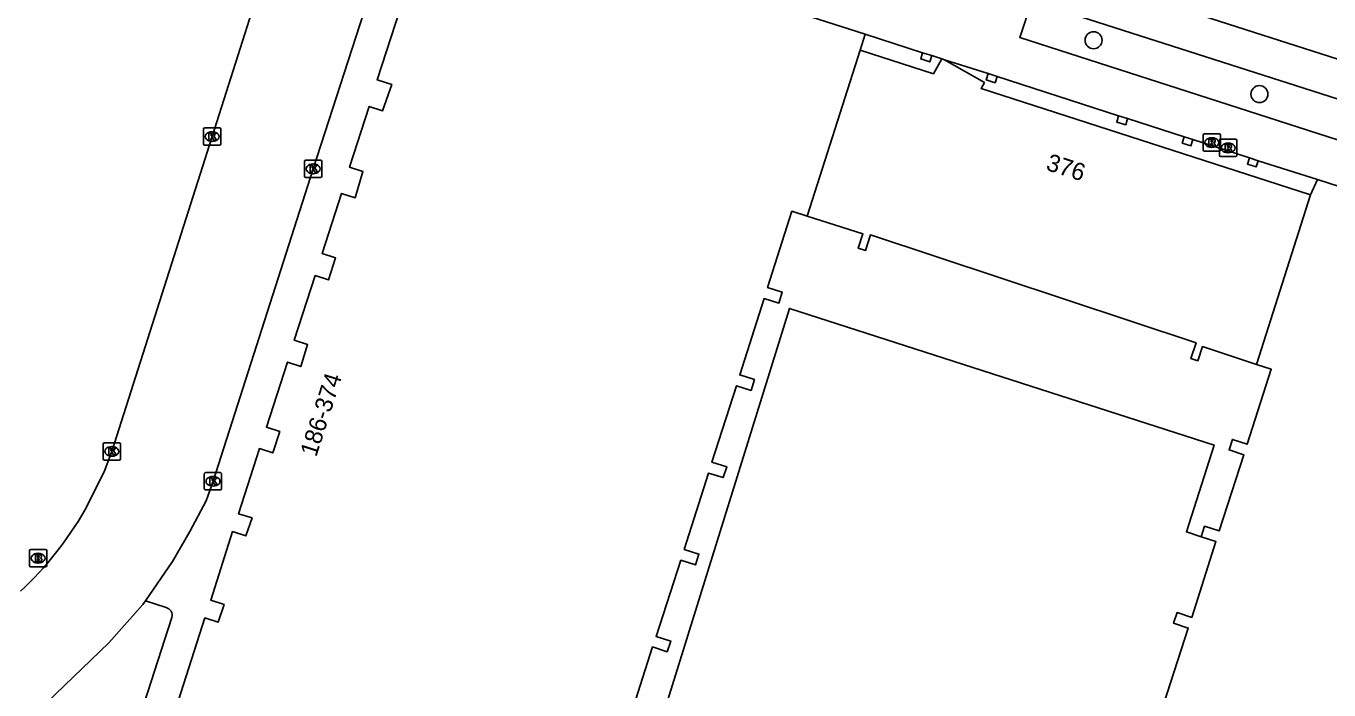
# Model space of a CAD drawing. Extents: x 160676 to 161153, y 383244 to 383713.
# Drawn here: x 160812.1 to 160887.3, y 383366.1 to 383404.4 of the extents above; entities that cross this region are included whole.
import ezdxf

# ---------------------------------------------------------------- set-up
doc = ezdxf.new("R2010")
doc.units = 0
for name, color, linetype in [('IMGEO_Boom', 7, 'Continuous'), ('IMGEO_Brandkraan', 7, 'Continuous'), ('IMGEO_Erf', 7, 'Continuous'), ('IMGEO_Kolk', 7, 'Continuous'), ('IMGEO_Muur', 7, 'Continuous'), ('IMGEO_Pand', 7, 'Continuous'), ('IMGEO_Pand_nummerreeks', 7, 'Continuous'), ('IMGEO_Parkeervlak_open', 7, 'Continuous'), ('IMGEO_Rijbaan_lokaal_open', 7, 'Continuous'), ('IMGEO_Rioolput', 7, 'Continuous'), ('IMGEO_Voetpad_open', 7, 'Continuous')]:
    doc.layers.add(name, color=color, linetype=linetype)

msp = doc.modelspace()

# ---------------------------------------------------------------- linework, layer by layer
at = {"layer": 'IMGEO_Boom'}
for centre in [(160873.692, 383403.537), (160883.26, 383400.432)]:
    msp.add_circle(centre, 0.489, dxfattribs=at)
at = {"layer": 'IMGEO_Brandkraan'}
for p, q in [((160812.259, 383373.243), (160812.259, 383374.095)), ((160812.334, 383374.169), (160813.186, 383374.169)), ((160812.747, 383373.949), (160812.772, 383373.949)), ((160813.26, 383374.095), (160813.26, 383373.243)), ((160813.186, 383373.169), (160812.334, 383373.169)), ((160812.77, 383373.389), (160812.745, 383373.389))]:
    msp.add_line(p, q, dxfattribs=at)
for points in [[(160812.259, 383373.243), (160812.259, 383374.095)], [(160812.334, 383374.169), (160813.186, 383374.169)], [(160812.607, 383373.869), (160812.607, 383373.469), (160812.82, 383373.469)], [(160812.838, 383373.869), (160812.607, 383373.869)], [(160813.26, 383374.095), (160813.26, 383373.243)], [(160813.186, 383373.169), (160812.334, 383373.169)], [(160812.786, 383373.788), (160812.732, 383373.788), (160812.732, 383373.712)], [(160812.732, 383373.712), (160812.785, 383373.712)], [(160812.794, 383373.636), (160812.732, 383373.636), (160812.732, 383373.555)], [(160812.732, 383373.555), (160812.794, 383373.555)]]:
    msp.add_lwpolyline(points, dxfattribs=at)
for centre, radius, start, end in [((160812.336, 383374.093), 0.0765, 91.55205, 178.44795), ((160812.336, 383374.093), 0.0765, 91.55205, 178.44795), ((160812.842, 383373.724), 0.145, 59.4692, 91.53667), ((160812.867, 383373.771), 0.0922, 285.51372, 58.15012), ((160813.184, 383374.093), 0.0765, 1.55205, 88.44795), ((160813.184, 383374.093), 0.0765, 1.55205, 88.44795), ((160812.336, 383373.245), 0.0765, 181.55205, 268.44795), ((160812.336, 383373.245), 0.0765, 181.55205, 268.44795), ((160812.787, 383373.75), 0.0379, 267.82845, 90.93552), ((160812.795, 383373.595), 0.0404, 269.87594, 90.50774), ((160812.826, 383373.72), 0.251, 268.66757, 293.53466), ((160812.872, 383373.579), 0.105, 301.31148, 78.98903), ((160813.184, 383373.245), 0.0765, 271.55205, 358.44795), ((160813.184, 383373.245), 0.0765, 271.55205, 358.44795)]:
    msp.add_arc(centre, radius, start, end, dxfattribs=at)
for centre, major_axis, ratio, start_param, end_param in [((160812.746, 383373.669), (-0.387, 0.002), 0.722429, 4.712389, 7.853982), ((160812.771, 383373.669), (-0.39, 0.002), 0.717154, 1.570796, 4.712389)]:
    msp.add_ellipse(centre, major_axis=major_axis, ratio=ratio, start_param=start_param, end_param=end_param, dxfattribs=at)
at = {"layer": 'IMGEO_Erf'}
msp.add_lwpolyline([(160879.905, 383374.906), (160879.048, 383375.181), (160880.657, 383380.189), (160856.132, 383388.071), (160842.086, 383342.926)], dxfattribs=at)
at = {"layer": 'IMGEO_Kolk'}
for p, q in [((160822.305, 383397.558), (160822.305, 383398.41)), ((160822.38, 383398.484), (160823.232, 383398.484)), ((160822.793, 383398.264), (160822.818, 383398.264)), ((160823.306, 383398.41), (160823.306, 383397.558)), ((160823.232, 383397.484), (160822.38, 383397.484)), ((160822.816, 383397.704), (160822.791, 383397.704)), ((160828.141, 383395.698), (160828.141, 383396.55)), ((160828.216, 383396.624), (160829.068, 383396.624)), ((160828.629, 383396.404), (160828.654, 383396.404)), ((160829.142, 383396.55), (160829.142, 383395.698)), ((160828.652, 383395.844), (160828.627, 383395.844)), ((160829.068, 383395.624), (160828.216, 383395.624)), ((160816.518, 383379.4), (160816.518, 383380.252)), ((160816.593, 383380.326), (160817.445, 383380.326)), ((160817.006, 383380.106), (160817.031, 383380.106)), ((160817.519, 383380.252), (160817.519, 383379.4)), ((160817.445, 383379.326), (160816.593, 383379.326)), ((160817.029, 383379.546), (160817.004, 383379.546)), ((160822.356, 383377.677), (160822.356, 383378.529)), ((160822.431, 383378.603), (160823.283, 383378.603)), ((160822.844, 383378.383), (160822.869, 383378.383)), ((160823.357, 383378.529), (160823.357, 383377.677)), ((160823.283, 383377.603), (160822.431, 383377.603)), ((160822.867, 383377.823), (160822.842, 383377.823))]:
    msp.add_line(p, q, dxfattribs=at)
for points in [[(160822.305, 383397.558), (160822.305, 383398.41)], [(160822.38, 383398.484), (160823.232, 383398.484)], [(160822.626, 383398.184), (160822.749, 383398.184), (160822.749, 383398.033), (160822.879, 383398.184), (160823.043, 383398.184), (160822.897, 383398.033), (160823.05, 383397.784), (160822.898, 383397.784), (160822.813, 383397.948), (160822.749, 383397.881), (160822.749, 383397.784), (160822.626, 383397.784), (160822.626, 383398.184)], [(160823.306, 383398.41), (160823.306, 383397.558)], [(160823.232, 383397.484), (160822.38, 383397.484)], [(160828.141, 383395.698), (160828.141, 383396.55)], [(160828.216, 383396.624), (160829.068, 383396.624)], [(160829.142, 383396.55), (160829.142, 383395.698)], [(160828.462, 383396.324), (160828.585, 383396.324), (160828.585, 383396.173), (160828.715, 383396.324), (160828.879, 383396.324), (160828.733, 383396.173), (160828.886, 383395.924), (160828.734, 383395.924), (160828.649, 383396.088), (160828.585, 383396.021), (160828.585, 383395.924), (160828.462, 383395.924), (160828.462, 383396.324)], [(160829.068, 383395.624), (160828.216, 383395.624)], [(160816.518, 383379.4), (160816.518, 383380.252)], [(160816.593, 383380.326), (160817.445, 383380.326)], [(160816.839, 383380.026), (160816.962, 383380.026), (160816.962, 383379.875), (160817.092, 383380.026), (160817.256, 383380.026), (160817.11, 383379.875), (160817.263, 383379.626), (160817.111, 383379.626), (160817.026, 383379.79), (160816.962, 383379.723), (160816.962, 383379.626), (160816.839, 383379.626), (160816.839, 383380.026)], [(160817.519, 383380.252), (160817.519, 383379.4)], [(160817.445, 383379.326), (160816.593, 383379.326)], [(160822.356, 383377.677), (160822.356, 383378.529)], [(160822.431, 383378.603), (160823.283, 383378.603)], [(160823.357, 383378.529), (160823.357, 383377.677)], [(160823.283, 383377.603), (160822.431, 383377.603)], [(160822.677, 383378.303), (160822.8, 383378.303), (160822.8, 383378.152), (160822.93, 383378.303), (160823.094, 383378.303), (160822.948, 383378.152), (160823.101, 383377.903), (160822.949, 383377.903), (160822.864, 383378.067), (160822.8, 383378), (160822.8, 383377.903), (160822.677, 383377.903), (160822.677, 383378.303)]]:
    msp.add_lwpolyline(points, dxfattribs=at)
for centre, start, end in [((160822.382, 383398.408), 91.55205, 178.44795), ((160822.382, 383398.408), 91.55205, 178.44795), ((160823.23, 383398.408), 1.55205, 88.44795), ((160823.23, 383398.408), 1.55205, 88.44795), ((160822.382, 383397.56), 181.55205, 268.44795), ((160822.382, 383397.56), 181.55205, 268.44795), ((160823.23, 383397.56), 271.55205, 358.44795), ((160823.23, 383397.56), 271.55205, 358.44795), ((160828.218, 383396.548), 91.55205, 178.44795), ((160828.218, 383396.548), 91.55205, 178.44795), ((160829.066, 383396.548), 1.55205, 88.44795), ((160829.066, 383396.548), 1.55205, 88.44795), ((160828.218, 383395.7), 181.55205, 268.44795), ((160828.218, 383395.7), 181.55205, 268.44795), ((160829.066, 383395.7), 271.55205, 358.44795), ((160829.066, 383395.7), 271.55205, 358.44795), ((160816.595, 383380.25), 91.55205, 178.44795), ((160816.595, 383380.25), 91.55205, 178.44795), ((160817.443, 383380.25), 1.55205, 88.44795), ((160817.443, 383380.25), 1.55205, 88.44795), ((160816.595, 383379.402), 181.55205, 268.44795), ((160816.595, 383379.402), 181.55205, 268.44795), ((160817.443, 383379.402), 271.55205, 358.44795), ((160817.443, 383379.402), 271.55205, 358.44795), ((160822.433, 383378.527), 91.55205, 178.44795), ((160822.433, 383378.527), 91.55205, 178.44795), ((160823.281, 383378.527), 1.55205, 88.44795), ((160823.281, 383378.527), 1.55205, 88.44795), ((160822.433, 383377.679), 181.55205, 268.44795), ((160822.433, 383377.679), 181.55205, 268.44795), ((160823.281, 383377.679), 271.55205, 358.44795), ((160823.281, 383377.679), 271.55205, 358.44795)]:
    msp.add_arc(centre, 0.0765, start, end, dxfattribs=at)
for centre, major_axis, ratio, start_param, end_param in [((160822.792, 383397.984), (-0.387, 0.002), 0.722429, 4.712389, 7.853982), ((160822.817, 383397.984), (-0.39, 0.002), 0.717154, 1.570796, 4.712389), ((160828.628, 383396.124), (-0.387, 0.002), 0.722429, 4.712389, 7.853982), ((160828.653, 383396.124), (-0.39, 0.002), 0.717154, 1.570796, 4.712389), ((160817.005, 383379.826), (-0.387, 0.002), 0.722429, 4.712389, 7.853982), ((160817.03, 383379.826), (-0.39, 0.002), 0.717154, 1.570796, 4.712389), ((160822.843, 383378.103), (-0.387, 0.002), 0.722429, 4.712389, 7.853982), ((160822.868, 383378.103), (-0.39, 0.002), 0.717154, 1.570796, 4.712389)]:
    msp.add_ellipse(centre, major_axis=major_axis, ratio=ratio, start_param=start_param, end_param=end_param, dxfattribs=at)
at = {"layer": 'IMGEO_Muur'}
msp.add_lwpolyline([(160841.04, 383343.261), (160842.086, 383342.926), (160856.132, 383388.071), (160880.657, 383380.189), (160879.048, 383375.181), (160879.905, 383374.906)], dxfattribs=at)
at = {"layer": 'IMGEO_Pand'}
for points in [[(160817.895, 383356.208), (160821.316, 383366.858), (160822.392, 383370.22), (160823.163, 383369.973), (160823.496, 383370.997), (160822.724, 383371.243), (160823.986, 383375.204), (160824.758, 383374.958), (160825.11, 383375.989), (160824.338, 383376.235), (160825.534, 383379.988), (160826.306, 383379.742), (160826.707, 383380.979), (160825.937, 383381.229), (160827.15, 383384.974), (160827.92, 383384.724), (160828.316, 383385.985), (160827.546, 383386.235), (160828.756, 383389.963), (160829.527, 383389.713), (160829.929, 383390.988), (160829.159, 383391.238), (160830.284, 383394.706), (160831.054, 383394.456), (160831.515, 383395.963), (160830.744, 383396.211), (160831.872, 383399.719), (160832.643, 383399.472), (160833.175, 383400.981), (160832.338, 383401.253), (160835.783, 383411.857)], [(160850.738, 383407.032), (160860.509, 383403.898)], [(160860.213, 383402.974), (160860.509, 383403.898)], [(160857.153, 383393.398), (160860.213, 383402.974)], [(160864.938, 383402.467), (160864.447, 383401.611), (160860.213, 383402.974)], [(160863.822, 383402.82), (160863.709, 383402.459), (160864.233, 383402.294), (160864.346, 383402.656)], [(160863.822, 383402.82), (160864.346, 383402.656)], [(160864.938, 383402.467), (160865.09, 383402.418)], [(160886.212, 383394.621), (160867.194, 383400.751), (160867.388, 383401.098), (160865.09, 383402.418)], [(160867.599, 383401.617), (160867.49, 383401.254), (160868.005, 383401.092), (160868.118, 383401.454)], [(160867.599, 383401.617), (160868.118, 383401.454)], [(160875.134, 383399.186), (160875.028, 383398.822), (160875.546, 383398.67), (160875.652, 383399.034)], [(160875.134, 383399.186), (160875.652, 383399.034)], [(160878.925, 383397.971), (160878.806, 383397.611), (160879.308, 383397.448), (160879.427, 383397.808)], [(160878.925, 383397.971), (160879.427, 383397.808)], [(160882.686, 383396.757), (160882.567, 383396.397), (160883.069, 383396.234), (160883.188, 383396.594)], [(160882.686, 383396.757), (160883.188, 383396.594)], [(160886.606, 383395.503), (160886.212, 383394.621)], [(160886.606, 383395.503), (160896.283, 383392.391), (160895.823, 383390.963), (160901.015, 383389.295), (160901.475, 383390.722), (160905.053, 383389.568), (160905.398, 383389.462)], [(160886.212, 383394.621), (160883.089, 383384.848)], [(160846.821, 383364.146), (160848.234, 383368.548), (160849.081, 383368.275), (160849.278, 383368.885), (160848.431, 383369.158), (160849.863, 383373.547), (160850.713, 383373.283), (160850.907, 383373.909), (160850.057, 383374.173), (160851.466, 383378.58), (160852.316, 383378.316), (160852.51, 383378.942), (160851.66, 383379.205), (160853.069, 383383.612), (160853.919, 383383.348), (160854.113, 383383.974), (160853.263, 383384.238), (160854.672, 383388.645), (160855.522, 383388.382), (160855.716, 383389.007), (160854.866, 383389.271), (160856.275, 383393.678), (160857.153, 383393.398)], [(160857.153, 383393.398), (160860.371, 383392.369), (160860.106, 383391.54), (160860.515, 383391.409), (160860.805, 383392.314), (160879.602, 383386.088), (160879.303, 383385.186), (160879.712, 383385.051), (160879.985, 383385.876), (160883.089, 383384.848)], [(160883.089, 383384.848), (160883.944, 383384.565), (160882.555, 383380.243), (160881.707, 383380.515), (160881.513, 383379.91), (160882.36, 383379.637), (160880.947, 383375.239), (160880.099, 383375.511), (160879.905, 383374.906)], [(160877.73, 383365.236), (160879.155, 383369.642), (160878.309, 383369.918), (160878.509, 383370.531), (160879.355, 383370.255), (160880.752, 383374.634), (160879.905, 383374.906)]]:
    msp.add_lwpolyline(points, dxfattribs=at)
at = {"layer": 'IMGEO_Parkeervlak_open'}
msp.add_lwpolyline([(160870.118, 383405.788), (160898.75, 383396.637)], dxfattribs=at)
at = {"layer": 'IMGEO_Rijbaan_lokaal_open'}
for points in [[(160834.558, 383435.125), (160833.651, 383432.112), (160831.814, 383426.328), (160828.462, 383415.776), (160822.806, 383397.984), (160817.019, 383379.826), (160816.581, 383378.652), (160815.453, 383376.434)], [(160834.694, 383414.833), (160828.642, 383396.124), (160822.857, 383378.103), (160822.464, 383376.968), (160821.528, 383375.201), (160820.52, 383373.47), (160818.954, 383371.207)], [(160899.445, 383398.723), (160870.773, 383407.909)], [(160806.021, 383358.402), (160806.548, 383358.908), (160816.836, 383368.789), (160818.816, 383371.007), (160818.954, 383371.207)]]:
    msp.add_lwpolyline(points, dxfattribs=at)
msp.add_arc((160797.755, 383386.651), 20.436, 313.21535, 330.00199, dxfattribs=at)
at = {"layer": 'IMGEO_Rioolput'}
for p, q in [((160880.01, 383397.212), (160880.01, 383398.064)), ((160880.085, 383398.138), (160880.937, 383398.138)), ((160880.498, 383397.918), (160880.523, 383397.918)), ((160881.011, 383398.064), (160881.011, 383397.212)), ((160880.521, 383397.358), (160880.496, 383397.358)), ((160880.953, 383396.902), (160880.953, 383397.754)), ((160881.028, 383397.828), (160881.88, 383397.828)), ((160881.441, 383397.608), (160881.466, 383397.608)), ((160881.954, 383397.754), (160881.954, 383396.902)), ((160880.937, 383397.138), (160880.085, 383397.138)), ((160881.88, 383396.828), (160881.028, 383396.828)), ((160881.464, 383397.048), (160881.439, 383397.048))]:
    msp.add_line(p, q, dxfattribs=at)
for points in [[(160880.01, 383397.212), (160880.01, 383398.064)], [(160880.085, 383398.138), (160880.937, 383398.138)], [(160881.011, 383398.064), (160881.011, 383397.212)], [(160880.599, 383397.836), (160880.347, 383397.838), (160880.347, 383397.438)], [(160880.347, 383397.438), (160880.471, 383397.438), (160880.471, 383397.6), (160880.482, 383397.6)], [(160880.525, 383397.757), (160880.471, 383397.757), (160880.471, 383397.676)], [(160880.471, 383397.676), (160880.523, 383397.676)], [(160880.529, 383397.571), (160880.6, 383397.438), (160880.74, 383397.438), (160880.675, 383397.564)], [(160880.953, 383396.902), (160880.953, 383397.754)], [(160881.028, 383397.828), (160881.88, 383397.828)], [(160881.542, 383397.526), (160881.29, 383397.528), (160881.29, 383397.128)], [(160881.29, 383397.128), (160881.414, 383397.128), (160881.414, 383397.29), (160881.425, 383397.29)], [(160881.468, 383397.447), (160881.414, 383397.447), (160881.414, 383397.366)], [(160881.414, 383397.366), (160881.466, 383397.366)], [(160881.472, 383397.261), (160881.543, 383397.128), (160881.683, 383397.128), (160881.618, 383397.254)], [(160881.954, 383397.754), (160881.954, 383396.902)], [(160880.937, 383397.138), (160880.085, 383397.138)], [(160881.88, 383396.828), (160881.028, 383396.828)]]:
    msp.add_lwpolyline(points, dxfattribs=at)
for centre, radius, start, end in [((160880.087, 383398.062), 0.0765, 91.55205, 178.44795), ((160880.087, 383398.062), 0.0765, 91.55205, 178.44795), ((160880.935, 383398.062), 0.0765, 1.55205, 88.44795), ((160880.935, 383398.062), 0.0765, 1.55205, 88.44795), ((160880.087, 383397.214), 0.0765, 181.55205, 268.44795), ((160880.087, 383397.214), 0.0765, 181.55205, 268.44795), ((160880.481, 383397.547), 0.0533, 26.02933, 88.69889), ((160880.507, 383397.865), 0.19, 274.7715, 282.96867), ((160880.531, 383397.661), 0.0964, 77.00612, 93.18647), ((160880.545, 383397.718), 0.0378, 276.66336, 79.67722), ((160880.598, 383397.726), 0.109, 350.36119, 89.41601), ((160880.596, 383397.726), 0.112, 277.58423, 350.98172), ((160880.58, 383397.511), 0.108, 29.51342, 73.79051), ((160880.935, 383397.214), 0.0765, 271.55205, 358.44795), ((160880.935, 383397.214), 0.0765, 271.55205, 358.44795), ((160881.03, 383397.752), 0.0765, 91.55205, 178.44795), ((160881.03, 383397.752), 0.0765, 91.55205, 178.44795), ((160881.424, 383397.237), 0.0533, 26.02933, 88.69889), ((160881.45, 383397.555), 0.19, 274.7715, 282.96867), ((160881.474, 383397.351), 0.0964, 77.00612, 93.18647), ((160881.488, 383397.408), 0.0378, 276.66336, 79.67722), ((160881.541, 383397.416), 0.109, 350.36119, 89.41601), ((160881.539, 383397.416), 0.112, 277.58423, 350.98172), ((160881.523, 383397.201), 0.108, 29.51342, 73.79051), ((160881.878, 383397.752), 0.0765, 1.55205, 88.44795), ((160881.878, 383397.752), 0.0765, 1.55205, 88.44795), ((160881.03, 383396.904), 0.0765, 181.55205, 268.44795), ((160881.03, 383396.904), 0.0765, 181.55205, 268.44795), ((160881.878, 383396.904), 0.0765, 271.55205, 358.44795), ((160881.878, 383396.904), 0.0765, 271.55205, 358.44795)]:
    msp.add_arc(centre, radius, start, end, dxfattribs=at)
for centre, major_axis, ratio, start_param, end_param in [((160880.497, 383397.638), (-0.387, 0.002), 0.722429, 4.712389, 7.853982), ((160880.522, 383397.638), (-0.39, 0.002), 0.717154, 1.570796, 4.712389), ((160881.44, 383397.328), (-0.387, 0.002), 0.722429, 4.712389, 7.853982), ((160881.465, 383397.328), (-0.39, 0.002), 0.717154, 1.570796, 4.712389)]:
    msp.add_ellipse(centre, major_axis=major_axis, ratio=ratio, start_param=start_param, end_param=end_param, dxfattribs=at)
at = {"layer": 'IMGEO_Voetpad_open'}
for points in [[(160898.75, 383396.637), (160898.106, 383394.467), (160869.425, 383403.701), (160870.118, 383405.788)], [(160860.509, 383403.898), (160863.822, 383402.82)], [(160864.346, 383402.656), (160864.938, 383402.467)], [(160865.09, 383402.418), (160867.599, 383401.617)], [(160868.118, 383401.454), (160875.134, 383399.186)], [(160875.652, 383399.034), (160878.925, 383397.971)], [(160879.427, 383397.808), (160882.686, 383396.757)], [(160883.188, 383396.594), (160886.606, 383395.503)], [(160818.954, 383371.207), (160820.15, 383370.824)], [(160820.49, 383370.251), (160818.286, 383363.462), (160816.31, 383364.162), (160815.328, 383360.895), (160817.277, 383360.223), (160815.278, 383354.045), (160813.56, 383354.584), (160812.694, 383351.868)]]:
    msp.add_lwpolyline(points, dxfattribs=at)
msp.add_arc((160820.021, 383370.36), 0.481, 346.90316, 74.46394, dxfattribs=at)

# ---------------------------------------------------------------- texts
at = {"layer": 'IMGEO_Pand_nummerreeks'}
for s, rotation, p in [('376', 342.23754, (160870.888, 383396.075)), ('186-374', 72.2117, (160828.814, 383379.468))]:
    msp.add_text(s, height=1, rotation=rotation, dxfattribs=at).set_placement(p)

doc.saveas('drawing.dxf')
